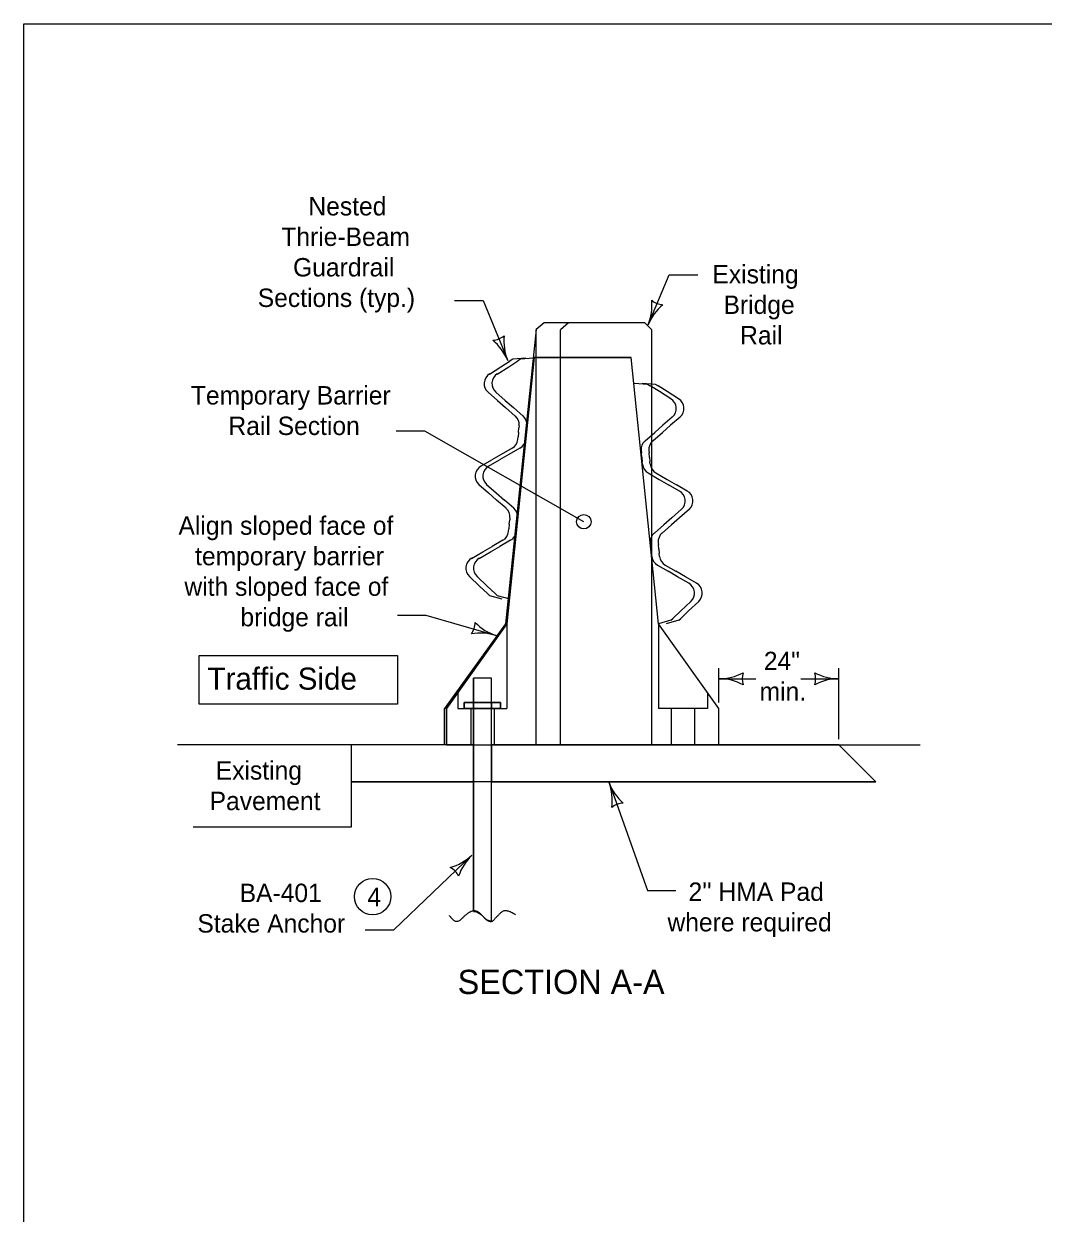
# Model space of a CAD drawing. Extents: x 10028 to 81668, y 3581 to 11018.
# Drawn here: x 20933 to 21774, y 8962 to 9944 of the extents above; entities that cross this region are included whole.
import ezdxf

# ---------------------------------------------------------------- set-up
doc = ezdxf.new("R2010")
doc.units = 0
for name, color, linetype in [('dsnCellsNorthArrow', 7, 'Continuous'), ('dsnTextTabulation', 7, 'Continuous'), ('Level 41', 7, 'Continuous'), ('Level 9', 7, 'Continuous'), ('SheetBorder', 7, 'Continuous')]:
    doc.layers.add(name, color=color, linetype=linetype)

msp = doc.modelspace()

# ---------------------------------------------------------------- linework, layer by layer
at = {"layer": 'dsnCellsNorthArrow'}
for p, q in [((21362.04, 9697.14), (21355.56, 9691.46)), ((21445.18, 9697.14), (21362.04, 9697.14)), ((21382.2, 9697.14), (21375.5, 9691.27)), ((21450.93, 9691.16), (21445.18, 9697.14)), ((21355.56, 9691.46), (21330.33, 9448.52)), ((21355.56, 9348.52), (21355.56, 9691.46)), ((21375.5, 9348.52), (21375.5, 9691.27)), ((21450.93, 9348.52), (21450.93, 9691.16)), ((21330.33, 9448.52), (21279.75, 9378.52)), ((21279.75, 9348.52), (21279.75, 9378.52))]:
    msp.add_line(p, q, dxfattribs=at)
at = {"layer": 'dsnTextTabulation'}
for p, q in [((21448.01, 9695.32), (21465.38, 9736.6)), ((21465.38, 9736.6), (21488.98, 9736.6)), ((21288.2, 9715.55), (21311.8, 9715.55)), ((21311.8, 9715.55), (21332.03, 9665.97)), ((21331.45, 9448.52), (21353.95, 9668.52)), ((21336.25, 9666.95), (21334.02, 9665.54)), ((21346.96, 9667.77), (21336.25, 9666.95)), ((21342.65, 9666.95), (21340.42, 9665.54)), ((21353.36, 9667.77), (21342.65, 9666.95)), ((21353.95, 9668.52), (21433.95, 9668.52)), ((21456.45, 9448.52), (21433.95, 9668.52)), ((21316.98, 9654.79), (21326.48, 9660.78)), ((21323.38, 9654.79), (21332.88, 9660.78)), ((21326.48, 9660.78), (21334.02, 9665.54)), ((21332.88, 9660.78), (21340.42, 9665.54)), ((21436.8, 9647.26), (21447.51, 9646.44)), ((21443.2, 9647.26), (21453.91, 9646.44)), ((21447.51, 9646.44), (21449.74, 9645.04)), ((21453.91, 9646.44), (21456.14, 9645.04)), ((21315.82, 9639.74), (21323.62, 9632.93)), ((21322.22, 9639.74), (21330.02, 9632.93)), ((21457.29, 9640.28), (21449.74, 9645.04)), ((21463.68, 9640.28), (21456.14, 9645.04)), ((21466.78, 9634.28), (21457.29, 9640.28)), ((21473.18, 9634.28), (21463.68, 9640.28)), ((21323.62, 9632.93), (21330.33, 9627.08)), ((21330.02, 9632.93), (21336.73, 9627.08)), ((21338.34, 9620.09), (21330.33, 9627.08)), ((21344.74, 9620.09), (21336.73, 9627.08)), ((21467.94, 9619.23), (21460.14, 9612.43)), ((21474.34, 9619.23), (21466.54, 9612.43)), ((21263.62, 9607.48), (21240.02, 9607.48)), ((21394.92, 9532.77), (21263.62, 9607.48)), ((21340.98, 9606.45), (21341.36, 9610.33)), ((21341.53, 9612.08), (21341.36, 9610.33)), ((21347.38, 9606.45), (21347.76, 9610.33)), ((21347.93, 9612.08), (21347.76, 9610.33)), ((21460.14, 9612.43), (21453.43, 9606.57)), ((21466.54, 9612.43), (21459.83, 9606.57)), ((21340.44, 9600.82), (21340.63, 9602.86)), ((21341, 9606.59), (21340.63, 9602.86)), ((21346.83, 9600.82), (21347.03, 9602.86)), ((21347.4, 9606.59), (21347.03, 9602.86)), ((21445.42, 9599.58), (21453.43, 9606.57)), ((21451.82, 9599.58), (21459.83, 9606.57)), ((21326.57, 9588.28), (21318.85, 9583.83)), ((21332.97, 9588.28), (21325.25, 9583.83)), ((21335.76, 9593.58), (21326.57, 9588.28)), ((21342.16, 9593.58), (21332.97, 9588.28)), ((21442.23, 9591.58), (21442.4, 9589.82)), ((21442.78, 9585.94), (21442.4, 9589.82)), ((21448.63, 9591.58), (21448.8, 9589.82)), ((21449.18, 9585.94), (21448.8, 9589.82)), ((21309.87, 9578.65), (21318.85, 9583.83)), ((21316.26, 9578.65), (21325.25, 9583.83)), ((21442.77, 9586.08), (21443.13, 9582.35)), ((21443.33, 9580.31), (21443.13, 9582.35)), ((21449.16, 9586.08), (21449.53, 9582.35)), ((21449.73, 9580.31), (21449.53, 9582.35)), ((21448.01, 9573.07), (21457.19, 9567.78)), ((21454.4, 9573.07), (21463.59, 9567.78)), ((21457.19, 9567.78), (21464.91, 9563.32)), ((21463.59, 9567.78), (21471.31, 9563.32)), ((21308.12, 9563.63), (21316.2, 9556.59)), ((21314.52, 9563.63), (21322.6, 9556.59)), ((21473.9, 9558.14), (21464.91, 9563.33)), ((21480.3, 9558.14), (21471.31, 9563.33)), ((21316.2, 9556.59), (21322.91, 9550.73)), ((21322.6, 9556.59), (21329.31, 9550.73)), ((21330.65, 9543.98), (21322.91, 9550.73)), ((21337.05, 9543.98), (21329.31, 9550.73)), ((21475.64, 9543.13), (21467.57, 9536.08)), ((21482.04, 9543.13), (21473.96, 9536.08)), ((21333.32, 9530.66), (21332.96, 9526.93)), ((21333.32, 9530.66), (21333.68, 9534.4)), ((21333.84, 9535.98), (21333.68, 9534.4)), ((21339.72, 9530.66), (21339.35, 9526.93)), ((21339.72, 9530.66), (21340.08, 9534.4)), ((21340.24, 9535.98), (21340.08, 9534.4)), ((21453.12, 9523.48), (21460.85, 9530.22)), ((21459.51, 9523.48), (21467.25, 9530.22)), ((21467.57, 9536.08), (21460.85, 9530.22)), ((21473.96, 9536.08), (21467.25, 9530.22)), ((21332.74, 9524.71), (21332.96, 9526.93)), ((21339.14, 9524.71), (21339.35, 9526.93)), ((21311.45, 9507.9), (21319.17, 9512.35)), ((21317.85, 9507.9), (21325.57, 9512.35)), ((21328.06, 9517.47), (21319.17, 9512.35)), ((21334.46, 9517.47), (21325.57, 9512.35)), ((21449.93, 9515.47), (21450.08, 9513.89)), ((21450.44, 9510.16), (21450.08, 9513.89)), ((21450.44, 9510.16), (21450.81, 9506.42)), ((21456.32, 9515.47), (21456.48, 9513.89)), ((21456.84, 9510.16), (21456.48, 9513.89)), ((21456.84, 9510.16), (21457.21, 9506.42)), ((21302.17, 9502.55), (21311.45, 9507.9)), ((21308.57, 9502.55), (21317.85, 9507.9)), ((21451.02, 9504.21), (21450.81, 9506.42)), ((21457.42, 9504.21), (21457.21, 9506.42)), ((21455.7, 9496.97), (21464.6, 9491.84)), ((21462.1, 9496.97), (21470.99, 9491.84)), ((21472.31, 9487.39), (21464.6, 9491.84)), ((21478.71, 9487.39), (21470.99, 9491.84)), ((21300.4, 9487.55), (21308.81, 9479.61)), ((21306.8, 9487.55), (21315.2, 9479.61)), ((21308.81, 9479.61), (21315.29, 9473.48)), ((21315.2, 9479.61), (21321.69, 9473.48)), ((21481.6, 9482.04), (21472.31, 9487.39)), ((21487.99, 9482.04), (21478.71, 9487.39)), ((21316.96, 9471.9), (21315.29, 9473.48)), ((21316.96, 9471.9), (21327.31, 9469.03)), ((21323.36, 9471.9), (21321.69, 9473.48)), ((21323.36, 9471.9), (21333.71, 9469.03)), ((21483.36, 9467.04), (21474.96, 9459.1)), ((21489.76, 9467.04), (21481.36, 9459.1)), ((21240.93, 9455.58), (21264.54, 9455.58)), ((21264.54, 9455.58), (21322.64, 9438.73)), ((21466.8, 9451.39), (21456.45, 9448.52)), ((21473.2, 9451.39), (21462.85, 9448.52)), ((21466.8, 9451.39), (21468.48, 9452.97)), ((21474.96, 9459.1), (21468.48, 9452.97)), ((21473.2, 9451.39), (21474.87, 9452.97)), ((21481.36, 9459.1), (21474.87, 9452.97)), ((21281.45, 9378.52), (21331.45, 9448.52)), ((21506.45, 9378.52), (21456.45, 9448.52)), ((21506.45, 9383.51), (21506.45, 9411.87)), ((21605.49, 9353.28), (21605.49, 9411.87)), ((21506.45, 9403.11), (21536.86, 9403.11)), ((21574.18, 9403.11), (21605.49, 9403.11)), ((21281.45, 9348.52), (21281.45, 9378.52)), ((21506.45, 9348.52), (21506.45, 9378.52)), ((21281.45, 9348.52), (21506.45, 9348.52)), ((21415.75, 9317.4), (21447.38, 9228.36)), ((21238.11, 9195.72), (21302.53, 9257.52)), ((21447.38, 9228.36), (21470.98, 9228.36)), ((21214.5, 9195.72), (21238.11, 9195.72))]:
    msp.add_line(p, q, dxfattribs=at)
msp.add_circle((21220.5, 9223.19), 15, dxfattribs=at)
for centre, radius, start, end in [((21408.65, 9711.35), 42.5, 337.83753, 5.91002), ((21461.46, 9728.32), 16.42, 230.10418, 265.57088), ((21487.37, 9679.28), 42.5, 129.76504, 157.83753), ((21318.57, 9698.97), 16.42, 274.46679, 309.93349), ((21371.38, 9682.03), 42.5, 174.12765, 202.20014), ((21292.68, 9649.92), 42.5, 22.20014, 50.27263), ((21288.71, 9449.63), 16.42, 324.45544, 359.92214), ((21309.64, 9398.27), 42.5, 72.18879, 100.26128), ((21335.64, 9479.19), 42.5, 224.1163, 252.18879), ((21506.45, 9445.61), 42.5, 270, 298.07249), ((21506.45, 9360.61), 42.5, 61.92751, 90), ((21542.09, 9403.11), 16.42, 162.26665, 197.73335), ((21569.85, 9403.11), 16.42, 342.26665, 17.73335), ((21605.49, 9445.61), 42.5, 241.92751, 270), ((21605.49, 9360.61), 42.5, 90, 118.07249), ((21455.63, 9332.08), 42.5, 200.20763, 228.28012), ((21375.86, 9302.72), 42.5, 352.13514, 20.20763), ((21428.06, 9283.96), 16.42, 92.47427, 127.94098), ((21273.1, 9288.19), 42.5, 285.73709, 313.80957), ((21331.95, 9226.85), 42.5, 133.80957, 161.88206), ((21276.81, 9232.85), 16.42, 26.07622, 61.54292)]:
    msp.add_arc(centre, radius, start, end, dxfattribs=at)
for centre, major_axis, start_param, end_param in [((21322.06, 9646.83), (9.43, -0.92), 2.229659, 4.096128), ((21328.46, 9646.83), (9.43, -0.92), 2.229659, 4.096128), ((21461.7, 9626.32), (-9.43, -0.92), 2.187057, 4.053527), ((21468.1, 9626.32), (-9.43, -0.92), 2.187057, 4.053527), ((21332.1, 9613), (9.43, -0.92), 0, 0.954538), ((21338.5, 9613), (9.43, -0.92), 0, 0.954538), ((21331, 9601.74), (-9.43, 0.92), 2.187055, 3.141593), ((21337.4, 9601.74), (-9.43, 0.92), 2.187055, 3.141593), ((21451.66, 9592.5), (-9.43, -0.92), 5.328647, 6.283185), ((21458.06, 9592.5), (-9.43, -0.92), 5.328647, 6.283185), ((21314.62, 9570.49), (-9.43, 0.92), 5.32865, 7.195119), ((21321.02, 9570.49), (-9.43, 0.92), 5.32865, 7.195119), ((21452.76, 9581.23), (9.43, 0.92), 3.141593, 4.096131), ((21459.16, 9581.23), (9.43, 0.92), 3.141593, 4.096131), ((21469.14, 9549.98), (9.43, 0.92), 5.371251, 7.237721), ((21475.54, 9549.98), (9.43, 0.92), 5.371251, 7.237721), ((21324.4, 9536.9), (9.43, -0.92), 0, 0.954538), ((21330.8, 9536.9), (9.43, -0.92), 0, 0.954538), ((21323.31, 9525.63), (-9.43, 0.92), 2.187055, 3.141593), ((21329.7, 9525.63), (-9.43, 0.92), 2.187055, 3.141593), ((21459.36, 9516.39), (-9.43, -0.92), 5.328647, 6.283185), ((21465.76, 9516.39), (-9.43, -0.92), 5.328647, 6.283185), ((21306.93, 9494.38), (-9.43, 0.92), 5.32865, 7.195119), ((21313.32, 9494.38), (-9.43, 0.92), 5.32865, 7.195119), ((21460.46, 9505.13), (9.43, 0.92), 3.141593, 4.096131), ((21466.86, 9505.13), (9.43, 0.92), 3.141593, 4.096131), ((21476.84, 9473.88), (9.43, 0.92), 5.371251, 7.237721), ((21483.23, 9473.88), (9.43, 0.92), 5.371251, 7.237721)]:
    msp.add_ellipse(centre, major_axis=major_axis, ratio=0.994906, start_param=start_param, end_param=end_param, dxfattribs=at)
at = {"layer": 'Level 41'}
for p, q in [((21331.45, 9448.52), (21331.45, 9378.52)), ((21456.45, 9448.52), (21456.45, 9378.52)), ((21290.98, 9391.86), (21290.98, 9378.52)), ((21496.92, 9391.86), (21496.92, 9378.52)), ((21290.98, 9378.52), (21331.45, 9378.52)), ((21301.62, 9378.52), (21301.62, 9348.52)), ((21320.82, 9378.52), (21320.82, 9348.52)), ((21496.92, 9378.52), (21456.45, 9378.52)), ((21467.09, 9378.52), (21467.09, 9348.52)), ((21486.29, 9378.52), (21486.29, 9348.52))]:
    msp.add_line(p, q, dxfattribs=at)
at = {"layer": 'Level 9'}
for p, q in [((21353.95, 9668.52), (21331.45, 9448.52)), ((21433.95, 9668.52), (21353.95, 9668.52)), ((21456.45, 9448.52), (21433.95, 9668.52)), ((21331.45, 9448.52), (21281.45, 9378.52)), ((21506.45, 9378.52), (21456.45, 9448.52)), ((21318.72, 9403.52), (21303.72, 9403.52)), ((21303.72, 9403.52), (21303.72, 9383.52)), ((21318.72, 9403.52), (21303.72, 9403.52)), ((21303.72, 9210.9), (21303.72, 9403.52)), ((21318.72, 9383.52), (21318.72, 9403.52)), ((21318.72, 9203.34), (21318.72, 9403.52)), ((21296.22, 9383.52), (21296.22, 9378.52)), ((21303.72, 9383.52), (21296.22, 9383.52)), ((21296.22, 9378.52), (21296.22, 9383.52)), ((21303.72, 9383.52), (21318.72, 9383.52)), ((21318.72, 9383.52), (21303.72, 9383.52)), ((21303.72, 9383.52), (21303.72, 9378.52)), ((21303.72, 9378.52), (21303.72, 9383.52)), ((21318.72, 9383.52), (21318.72, 9378.52)), ((21318.72, 9378.52), (21318.72, 9383.52)), ((21281.45, 9378.52), (21281.45, 9348.52)), ((21296.22, 9378.52), (21303.72, 9378.52)), ((21318.72, 9378.52), (21303.72, 9378.52)), ((21303.72, 9378.52), (21303.72, 9210.9)), ((21303.72, 9378.52), (21318.72, 9378.52)), ((21318.72, 9203.34), (21318.72, 9378.52)), ((21318.72, 9378.52), (21326.22, 9378.52)), ((21506.45, 9348.52), (21506.45, 9378.52)), ((21202.74, 9348.52), (21059.32, 9348.52)), ((21202.74, 9348.52), (21202.74, 9318.08)), ((21281.45, 9348.52), (21202.74, 9348.52)), ((21281.45, 9348.52), (21202.74, 9348.52)), ((21202.74, 9348.52), (21202.74, 9280.52)), ((21301.62, 9348.52), (21281.45, 9348.52)), ((21281.45, 9348.52), (21506.45, 9348.52)), ((21303.72, 9348.52), (21301.62, 9348.52)), ((21303.72, 9318.08), (21303.72, 9348.52)), ((21320.82, 9348.52), (21318.72, 9348.52)), ((21318.72, 9348.52), (21318.72, 9318.08)), ((21467.09, 9348.52), (21320.82, 9348.52)), ((21486.29, 9348.52), (21467.09, 9348.52)), ((21506.45, 9348.52), (21486.29, 9348.52)), ((21605.49, 9348.52), (21506.45, 9348.52)), ((21506.45, 9348.52), (21672.54, 9348.52)), ((21635.93, 9318.08), (21605.49, 9348.52)), ((21605.49, 9348.52), (21635.93, 9318.08)), ((21202.74, 9318.08), (21303.72, 9318.08)), ((21635.93, 9318.08), (21202.74, 9318.08)), ((21318.72, 9318.08), (21635.93, 9318.08)), ((21202.74, 9280.52), (21072.29, 9280.52))]:
    msp.add_line(p, q, dxfattribs=at)
msp.add_lwpolyline([(21077.34, 9422.22), (21241, 9422.22), (21241, 9382.22), (21077.34, 9382.22)], close=True, dxfattribs=at)
for points in [[(21296.22, 9383.52), (21326.22, 9383.52), (21326.22, 9378.52), (21296.22, 9378.52)], [(21326.22, 9378.52), (21326.22, 9383.52), (21318.72, 9383.52)]]:
    msp.add_lwpolyline(points, dxfattribs=at)
msp.add_circle((21394.92, 9532.77), 5.96, dxfattribs=at)
for points, degree in [([(21338.45, 9208.16), (21330.24, 9213.53), (21323.29, 9206.9), (21317.3, 9200.27), (21306.56, 9212.9), (21298.35, 9209.42), (21290.15, 9200.59), (21283.83, 9207.53), (21283.89, 9207.51)], 2), ([(21303.72, 9210.9), (21304.77, 9210.96), (21308.85, 9210.2), (21314.73, 9203.29), (21318.02, 9203.17), (21318.72, 9203.34)], 3)]:
    msp.add_open_spline(points, degree=degree, dxfattribs=at)
at = {"layer": 'SheetBorder'}
msp.add_lwpolyline([(20932.52, 9944.02), (24067.53, 9944.02), (24067.53, 7924.02), (20932.52, 7924.02)], close=True, dxfattribs=at)

# ---------------------------------------------------------------- texts
at = {"layer": 'dsnCellsNorthArrow'}
for s, height, p in [('Nested ', 15.2, (21167.5, 9785.75)), ('Thrie-Beam', 15.2, (21145.16, 9760.55)), ('Guardrail ', 15.2, (21154.84, 9735.35)), ('Existing', 15.2, (21501.07, 9729.6)), ('Sections (typ.)', 15.2, (21125.69, 9710.15)), ('Bridge', 15.2, (21510.24, 9704.4)), ('Rail', 15.2, (21523.94, 9679.2)), ('Temporary Barrier', 15.2, (21070.51, 9629.6)), ('Rail Section', 15.2, (21101.46, 9604.4)), ('Align sloped face of', 15.2, (21060.22, 9522.02)), ('temporary barrier', 15.2, (21073.97, 9496.82)), ('with sloped face of ', 15.2, (21065.13, 9471.62)), ('bridge rail', 15.2, (21111.39, 9446.42)), ('24"', 15.2, (21543.51, 9410.21)), ('Traffic Side', 18.24, (21084.19, 9394.07)), ('min.', 15.2, (21540.01, 9385.01)), ('Existing', 15.2, (21091.02, 9319.82)), ('Pavement', 15.2, (21085.96, 9294.62)), ('BA-401', 15.2, (21110.76, 9218.68)), ("2'' HMA Pad", 15.2, (21481.35, 9219.66)), ('Stake Anchor', 15.2, (21075.85, 9193.48)), ('where required', 15.2, (21463.97, 9194.46)), ('SECTION A-A', 20, (21290.71, 9142.74))]:
    msp.add_text(s, height=height, dxfattribs=at).set_placement(p)
at = {"layer": 'dsnTextTabulation'}
msp.add_text('4', height=15.2, dxfattribs=at).set_placement((21216.13, 9215.29))

doc.saveas('drawing.dxf')
